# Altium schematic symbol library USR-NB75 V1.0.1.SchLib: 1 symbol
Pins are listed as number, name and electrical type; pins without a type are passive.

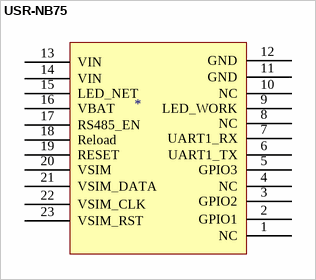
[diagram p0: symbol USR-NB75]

## USR-NB75
designator *
pins: 1 NC, 2 GPIO1, 3 GPIO2, 4 NC, 5 GPIO3, 6 UART1_TX, 7 UART1_RX, 8 NC, 9 LED_WORK, 10 NC, 11 GND, 12 GND, 13 VIN, 14 VIN, 15 LED_NET, 16 VBAT, 17 RS485_EN, 18 Reload, 19 RESET, 20 VSIM, 21 VSIM_DATA, 22 VSIM_CLK, 23 VSIM_RST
